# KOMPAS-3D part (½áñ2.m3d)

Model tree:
1. Эскиз:1
2. Операция выдавливания:1
     Расстояние 1 = 20
3. Эскиз:2
4. Операция выдавливания:2
     Расстояние 1 = 400
5. Эскиз:3
6. Вырезать элемент выдавливания:1
     Расстояние 1 = 70
7. Эскиз:4
8. Вырезать элемент выдавливания:2
     Расстояние 1 = 2
9. Эскиз:5
10. Эскиз:11
11. Вырезать элемент выдавливания:7
     Расстояние 1 = 30
12. Эскиз:12
13. Вырезать элемент выдавливания:8
     Расстояние 1 = 30
